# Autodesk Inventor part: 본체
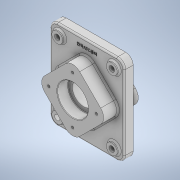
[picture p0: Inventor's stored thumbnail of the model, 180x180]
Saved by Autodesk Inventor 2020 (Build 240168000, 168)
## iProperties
Created: 2021-07
Part Number: 본체
Material: 일반
Document SubType Name: Modeling
Designer: Owner
Density: 1 g/cm^3
Appearance: 기본값
Mass: 807.977 g
Surface Area: 961.758 cm^2
Volume: 807.977 cm^3
Author: Owner
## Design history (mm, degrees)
sketch "스케치1"
  geometry: L1 (-75, -90)-(75, -90); L2 (75, -90)-(75, 90); L3 (75, 90)-(-75, 90); L4 (-75, 90)-(-75, -90); L5 (-75, -90)-(75, 90); L6 (75, -90)-(-75, 90); 1 further point
  constraints: 12 end point, 2 midpoint, 2 parallel, 1 horizontal, 1 perpendicular
  dimensions: "d0" = 150 distance of L3.end L2.end; "d1" = 180 distance of L2.end L1.end
extrude "돌출1" new body sketch "스케치1" stored distance "d2" = 18; taper "d3" = 0 deg
sketch "스케치2"
  geometry: L1 (-70.711, 0)-(0, 70.711); L2 (0, 70.711)-(70.711, 0); L3 (70.711, 0)-(0, -70.711); L4 (0, -70.711)-(-70.711, 0); L5 (-70.711, 0)-(70.711, 0); L6 (0, 70.711)-(0, -70.711); 2 further points
  constraints: 12 end point, 2 horizontal alignment, 2 midpoint, 2 parallel, 2 vertical alignment, 1 perpendicular
  dimensions: "d4" = 100 distance of L1.end L2.end; "d5" = 100 distance of L3.end L1.start (derived)
extrude "돌출2" join sketch "스케치2" distance "d6" = 29; taper "d7" = 0 deg
sketch "스케치3"
  geometry: L1 (-70.711, 0)-(0, 70.711); L2 (0, 70.711)-(70.711, 0); L3 (70.711, 0)-(0, -70.711); L4 (0, -70.711)-(-70.711, 0); L5 (-70.711, 0)-(70.711, 0); L6 (0, 70.711)-(0, -70.711); 2 further points
  constraints: 12 end point, 2 horizontal alignment, 2 midpoint, 2 parallel, 2 vertical alignment, 1 perpendicular
  dimensions: "d8" = 100 distance of L1.end L2.end; "d9" = 100 distance of L3.end L1.start (derived)
extrude "돌출3" join sketch "스케치3" distance "d10" = 23; taper "d11" = 0 deg
sketch "스케치5"
  geometry: C1 r 31 at (0, 0); 1 further point
  constraints: 1 centre point, 1 coincident
  dimensions: "d15" = 62 diameter of C1
extrude "돌출5" cut sketch "스케치5" distance "d16" = 22; taper "d17" = 0 deg
sketch "스케치6"
  geometry: C1 r 31 at (0, 0); 1 further point
  constraints: 1 centre point, 1 coincident
  dimensions: "d18" = 62 diameter of C1
extrude "돌출6" cut sketch "스케치6" distance "d19" = 22; taper "d20" = 0 deg
sketch "스케치7"
  geometry: C1 r 22.5 at (0, 0); 1 further point
  constraints: 1 centre point, 1 coincident
  dimensions: "d21" = 45 diameter of C1
extrude "돌출7" cut sketch "스케치7" extent not by distance; stored distance "d22" = 22; taper "d23" = 0 deg
sketch "스케치8"
  geometry: C1 r 31 at (0, 0) reference; 5 further points
  constraints: 2 horizontal alignment, 2 vertical alignment
  dimensions: "d24" = 48 distance of point (0, 0) point (0, 48); "d25" = 48 distance of point (0, -48) point (0, 0); "d26" = 48 distance of point (0, 0) point (48, 0); "d27" = 48 distance of point (0, 0) point (-48, 0)
hole "구멍1" sketch "스케치8" at (0, 48), (-48, 0), (48, 0), (0, -48) diameter "d28" = 4.917; stored, may be unused: countersink angle "d32" = 90 deg, drill point angle "d34" = 118 deg; dims "d29" = 10, "d30" = 4, "d31" = 2, "d33" = 13
fillet "모깎기1" dims "d42" = 15
fillet "모깎기2" dims "d52" = 20
chamfer "모따기1" distance "d53" = 1; stored, may be unused: second distance "d54" = 2, angle "d55" = 45 deg
fillet "모깎기3" dims "d56" = 1
fillet "모깎기4" dims "d57" = 3
fillet "모깎기5" dims "d58" = 3
fillet "모깎기6" dims "d59" = 3
sketch "스케치14"
  geometry: C1 r 11 at (-55, 70); C2 r 11 at (55, 70); C3 r 11 at (55, -70); C4 r 11 at (-55, -70); 1 further point
  constraints: 4 centre point
  dimensions: "d73" = 55 horizontal distance of point (0, 0) C2.centre; "d74" = 55 horizontal distance of C1.centre point (0, 0); "d75" = 55 horizontal distance of C4.centre point (0, 0); "d76" = 55 horizontal distance of C3.centre point (0, 0); "d77" = 70 vertical distance of point (0, 0) C2.centre; "d78" = 70 vertical distance of C3.centre point (0, 0); "d79" = 70 vertical distance of point (0, 0) C1.centre; "d80" = 70 vertical distance of C4.centre point (0, 0); "d81" = 22 diameter of C1; "d82" = 22 diameter of C2; "d83" = 22 diameter of C3; "d84" = 22 diameter of C4
extrude "돌출12" join sketch "스케치14" distance "d85" = 5; taper "d86" = 0 deg
sketch "스케치15"
  geometry: C1 r 11 at (0, 0) reference; C2 r 11 at (0, 0) reference; C3 r 5.5 at (0, 0); 1 further point
  constraints: 1 centre point, 1 coincident
  dimensions: "d87" = 11 diameter of C3
extrude "돌출13" cut sketch "스케치15" distance "d88" = 23; taper "d89" = 0 deg
fillet "모깎기7" dims "d90" = 3
sketch "스케치16"
  geometry: L1 (60, 90)-(-60, 90) reference; 2 further points
  constraints: 1 vertical alignment, 1 other
  dimensions: "d91" = 15 distance from line of point (0, 75) L1
feature "엠보싱1" sketch "스케치16" dims "d0" = 150, "d1" = 180, "d92" = 0.5, "d93" = 0
sketch "스케치17"
  geometry: 1 further point
sketch "스케치18"
  geometry: C1 r 22.5 at (0, 0) reference; C2 r 48 at (0, 0); C3 r 2.458 at (0, 48) reference; C4 r 2.458 at (-48, 0) reference; C5 r 2.458 at (0, -48) reference; C6 r 2.458 at (48, 0) reference; 5 further points
  constraints: 5 coincident, 1 centre point
  dimensions: "d94" = 96 diameter of C2
hole "구멍3" sketch "스케치18" at (0, 48), (48, 0), (0, -48), (-48, 0) diameter "d95" = 4.917; stored, may be unused: countersink angle "d99" = 90 deg, drill point angle "d101" = 118 deg; dims "d96" = 10, "d97" = 4, "d98" = 2, "d100" = 13
node "솔리드1"
mirror "미러5"
mirror "미러6"
feature "A9D066F2-1C7D-4E18-AEED-F7BC21143FA4" dims "d28" = 4.917, "d29" = 10, "d30" = 4, "d31" = 2, "d32" = 90 deg, "d33" = 13, "d34" = 118 deg
